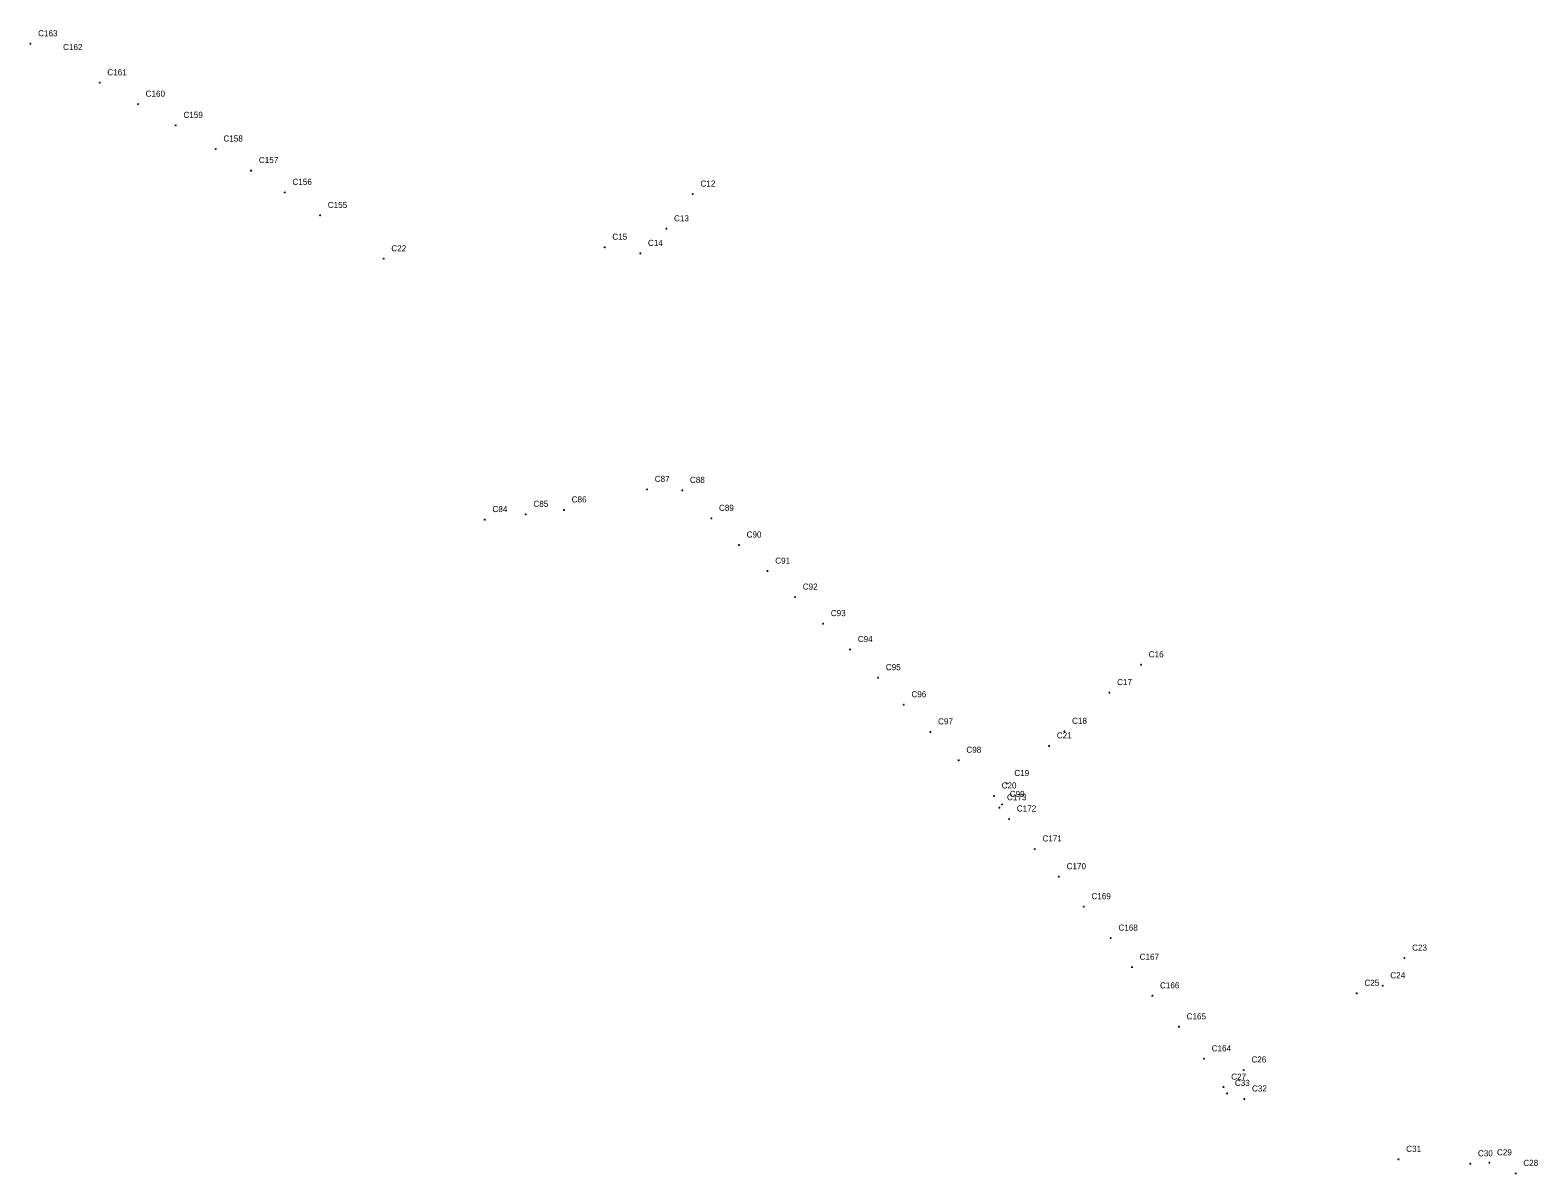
# Model space of a CAD drawing. Extents: x 1725610 to 1734530, y 649909 to 662665.
# Drawn here: x 1730600 to 1731594, y 651651 to 652405 of the extents above; entities that cross this region are included whole.
import ezdxf

# ---------------------------------------------------------------- set-up
doc = ezdxf.new("R2010")
doc.units = 0
doc.layers.add('SURVEY - DRAINAGE - Storm Sewer - Points - Locators', color=7, linetype='Continuous')
doc.layers.add('SURVEY - DRAINAGE - Storm Sewer - Points - Numbers', color=7, linetype='Continuous')

msp = doc.modelspace()

# ---------------------------------------------------------------- linework, layer by layer
at = {"layer": 'SURVEY - DRAINAGE - Storm Sewer - Points - Locators'}
for p, q in [((1730600.75, 652395.63), (1730600.25, 652395.63)), ((1730600.5, 652395.38), (1730600.5, 652395.88)), ((1730600.5, 652395.63), (1730600.5, 652395.63)), ((1730600.5, 652395.63), (1730600.5, 652395.63)), ((1730646.36, 652369.89), (1730645.86, 652369.89)), ((1730646.11, 652369.64), (1730646.11, 652370.14)), ((1730646.11, 652369.89), (1730646.11, 652369.89)), ((1730646.11, 652369.89), (1730646.11, 652369.89)), ((1730671.62, 652355.83), (1730671.12, 652355.83)), ((1730671.37, 652355.58), (1730671.37, 652356.08)), ((1730671.37, 652355.83), (1730671.37, 652355.83)), ((1730671.37, 652355.83), (1730671.37, 652355.83)), ((1730696.58, 652341.83), (1730696.08, 652341.83)), ((1730696.33, 652341.58), (1730696.33, 652342.08)), ((1730696.33, 652341.83), (1730696.33, 652341.83)), ((1730696.33, 652341.83), (1730696.33, 652341.83)), ((1730722.89, 652326.25), (1730722.39, 652326.25)), ((1730722.64, 652326), (1730722.64, 652326.5)), ((1730722.64, 652326.25), (1730722.64, 652326.25)), ((1730722.64, 652326.25), (1730722.64, 652326.25)), ((1730746.28, 652312.03), (1730745.78, 652312.03)), ((1730746.03, 652311.78), (1730746.03, 652312.28)), ((1730746.03, 652312.03), (1730746.03, 652312.03)), ((1730746.03, 652312.03), (1730746.03, 652312.03)), ((1730768.42, 652297.68), (1730767.92, 652297.68)), ((1730768.17, 652297.43), (1730768.17, 652297.93)), ((1730768.17, 652297.68), (1730768.17, 652297.68)), ((1730768.17, 652297.68), (1730768.17, 652297.68)), ((1731037.37, 652296.54), (1731036.87, 652296.54)), ((1731037.12, 652296.29), (1731037.12, 652296.79)), ((1731037.12, 652296.54), (1731037.12, 652296.54)), ((1731037.12, 652296.54), (1731037.12, 652296.54)), ((1730791.71, 652282.41), (1730791.21, 652282.41)), ((1730791.46, 652282.16), (1730791.46, 652282.66)), ((1730791.46, 652282.41), (1730791.46, 652282.41)), ((1730791.46, 652282.41), (1730791.46, 652282.41)), ((1731019.9, 652273.62), (1731019.4, 652273.62)), ((1731019.65, 652273.37), (1731019.65, 652273.87)), ((1731019.65, 652273.62), (1731019.65, 652273.62)), ((1731019.65, 652273.62), (1731019.65, 652273.62)), ((1730833.34, 652253.6), (1730833.34, 652254.1)), ((1730979.24, 652261.48), (1730978.74, 652261.48)), ((1730978.99, 652261.23), (1730978.99, 652261.73)), ((1730978.99, 652261.48), (1730978.99, 652261.48)), ((1730978.99, 652261.48), (1730978.99, 652261.48)), ((1731002.73, 652257.43), (1731002.23, 652257.43)), ((1731002.48, 652257.18), (1731002.48, 652257.68)), ((1731002.48, 652257.43), (1731002.48, 652257.43)), ((1731002.48, 652257.43), (1731002.48, 652257.43)), ((1730833.59, 652253.85), (1730833.09, 652253.85)), ((1730833.34, 652253.85), (1730833.34, 652253.85)), ((1730833.34, 652253.85), (1730833.34, 652253.85)), ((1731007.22, 652101.8), (1731006.72, 652101.8)), ((1731006.97, 652101.55), (1731006.97, 652102.05)), ((1731006.97, 652101.8), (1731006.97, 652101.8)), ((1731006.97, 652101.8), (1731006.97, 652101.8)), ((1731030.4, 652101.15), (1731029.9, 652101.15)), ((1731030.15, 652100.9), (1731030.15, 652101.4)), ((1731030.15, 652101.15), (1731030.15, 652101.15)), ((1731030.15, 652101.15), (1731030.15, 652101.15)), ((1730927.24, 652085.37), (1730926.74, 652085.37)), ((1730926.99, 652085.12), (1730926.99, 652085.62)), ((1730926.99, 652085.37), (1730926.99, 652085.37)), ((1730926.99, 652085.37), (1730926.99, 652085.37)), ((1730952.44, 652088.29), (1730951.94, 652088.29)), ((1730952.19, 652088.04), (1730952.19, 652088.54)), ((1730952.19, 652088.29), (1730952.19, 652088.29)), ((1730952.19, 652088.29), (1730952.19, 652088.29)), ((1730900.25, 652081.91), (1730899.75, 652081.91)), ((1730900, 652081.66), (1730900, 652082.16)), ((1730900, 652081.91), (1730900, 652081.91)), ((1730900, 652081.91), (1730900, 652081.91)), ((1731049.55, 652082.74), (1731049.05, 652082.74)), ((1731049.3, 652082.49), (1731049.3, 652082.99)), ((1731049.3, 652082.74), (1731049.3, 652082.74)), ((1731049.3, 652082.74), (1731049.3, 652082.74)), ((1731067.52, 652064.9), (1731067.52, 652065.4)), ((1731067.77, 652065.15), (1731067.27, 652065.15)), ((1731067.52, 652065.15), (1731067.52, 652065.15)), ((1731067.52, 652065.15), (1731067.52, 652065.15)), ((1731086.63, 652047.91), (1731086.13, 652047.91)), ((1731086.38, 652047.66), (1731086.38, 652048.16)), ((1731086.38, 652047.91), (1731086.38, 652047.91)), ((1731086.38, 652047.91), (1731086.38, 652047.91)), ((1731104.77, 652030.8), (1731104.27, 652030.8)), ((1731104.52, 652030.55), (1731104.52, 652031.05)), ((1731104.52, 652030.8), (1731104.52, 652030.8)), ((1731104.52, 652030.8), (1731104.52, 652030.8)), ((1731123.26, 652013.31), (1731122.76, 652013.31)), ((1731123.01, 652013.06), (1731123.01, 652013.56)), ((1731123.01, 652013.31), (1731123.01, 652013.31)), ((1731123.01, 652013.31), (1731123.01, 652013.31)), ((1731141.07, 651996.21), (1731140.57, 651996.21)), ((1731140.82, 651995.96), (1731140.82, 651996.46)), ((1731140.82, 651996.21), (1731140.82, 651996.21)), ((1731140.82, 651996.21), (1731140.82, 651996.21)), ((1731332.82, 651986.16), (1731332.32, 651986.16)), ((1731332.57, 651985.91), (1731332.57, 651986.41)), ((1731332.57, 651986.16), (1731332.57, 651986.16)), ((1731332.57, 651986.16), (1731332.57, 651986.16)), ((1731159.54, 651977.67), (1731159.04, 651977.67)), ((1731159.29, 651977.42), (1731159.29, 651977.92)), ((1731159.29, 651977.67), (1731159.29, 651977.67)), ((1731159.29, 651977.67), (1731159.29, 651977.67)), ((1731311.98, 651967.82), (1731311.48, 651967.82)), ((1731311.73, 651967.57), (1731311.73, 651968.07)), ((1731311.73, 651967.82), (1731311.73, 651967.82)), ((1731311.73, 651967.82), (1731311.73, 651967.82)), ((1731176.4, 651959.82), (1731175.9, 651959.82)), ((1731176.15, 651959.57), (1731176.15, 651960.07)), ((1731176.15, 651959.82), (1731176.15, 651959.82)), ((1731176.15, 651959.82), (1731176.15, 651959.82)), ((1731193.97, 651941.91), (1731193.47, 651941.91)), ((1731193.72, 651941.66), (1731193.72, 651942.16)), ((1731193.72, 651941.91), (1731193.72, 651941.91)), ((1731193.72, 651941.91), (1731193.72, 651941.91)), ((1731282.27, 651942.28), (1731281.77, 651942.28)), ((1731282.02, 651942.03), (1731282.02, 651942.53)), ((1731282.02, 651942.28), (1731282.02, 651942.28)), ((1731282.02, 651942.28), (1731282.02, 651942.28)), ((1731272.21, 651932.68), (1731271.71, 651932.68)), ((1731271.96, 651932.43), (1731271.96, 651932.93)), ((1731271.96, 651932.68), (1731271.96, 651932.68)), ((1731271.96, 651932.68), (1731271.96, 651932.68)), ((1731212.61, 651923.22), (1731212.11, 651923.22)), ((1731212.36, 651922.97), (1731212.36, 651923.47)), ((1731212.36, 651923.22), (1731212.36, 651923.22)), ((1731212.36, 651923.22), (1731212.36, 651923.22)), ((1731244.24, 651907.88), (1731243.74, 651907.88)), ((1731243.99, 651907.63), (1731243.99, 651908.13)), ((1731243.99, 651907.88), (1731243.99, 651907.88)), ((1731243.99, 651907.88), (1731243.99, 651907.88)), ((1731235.86, 651899.68), (1731235.36, 651899.68)), ((1731235.61, 651899.43), (1731235.61, 651899.93)), ((1731235.61, 651899.68), (1731235.61, 651899.68)), ((1731235.61, 651899.68), (1731235.61, 651899.68)), ((1731239.39, 651891.92), (1731238.89, 651891.92)), ((1731239.14, 651891.67), (1731239.14, 651892.17)), ((1731239.14, 651891.92), (1731239.14, 651891.92)), ((1731239.14, 651891.92), (1731239.14, 651891.92)), ((1731241.21, 651894.09), (1731240.71, 651894.09)), ((1731240.96, 651893.84), (1731240.96, 651894.34)), ((1731240.96, 651894.09), (1731240.96, 651894.09)), ((1731240.96, 651894.09), (1731240.96, 651894.09)), ((1731245.9, 651884.48), (1731245.4, 651884.48)), ((1731245.65, 651884.23), (1731245.65, 651884.73)), ((1731245.65, 651884.48), (1731245.65, 651884.48)), ((1731245.65, 651884.48), (1731245.65, 651884.48)), ((1731262.75, 651864.73), (1731262.25, 651864.73)), ((1731262.5, 651864.48), (1731262.5, 651864.98)), ((1731262.5, 651864.73), (1731262.5, 651864.73)), ((1731262.5, 651864.73), (1731262.5, 651864.73)), ((1731278.43, 651846.19), (1731278.43, 651846.69)), ((1731278.68, 651846.44), (1731278.18, 651846.44)), ((1731278.43, 651846.44), (1731278.43, 651846.44)), ((1731278.43, 651846.44), (1731278.43, 651846.44)), ((1731295.08, 651826.68), (1731294.58, 651826.68)), ((1731294.83, 651826.43), (1731294.83, 651826.93)), ((1731294.83, 651826.68), (1731294.83, 651826.68)), ((1731294.83, 651826.68), (1731294.83, 651826.68)), ((1731312.84, 651805.95), (1731312.34, 651805.95)), ((1731312.59, 651805.7), (1731312.59, 651806.2)), ((1731312.59, 651805.95), (1731312.59, 651805.95)), ((1731312.59, 651805.95), (1731312.59, 651805.95)), ((1731326.59, 651786.51), (1731326.59, 651787.01)), ((1731506.42, 651792.75), (1731505.92, 651792.75)), ((1731506.17, 651792.5), (1731506.17, 651793)), ((1731506.17, 651792.75), (1731506.17, 651792.75)), ((1731506.17, 651792.75), (1731506.17, 651792.75)), ((1731326.84, 651786.76), (1731326.34, 651786.76)), ((1731326.59, 651786.76), (1731326.59, 651786.76)), ((1731326.59, 651786.76), (1731326.59, 651786.76)), ((1731340.25, 651767.87), (1731339.75, 651767.87)), ((1731340, 651767.62), (1731340, 651768.12)), ((1731340, 651767.87), (1731340, 651767.87)), ((1731340, 651767.87), (1731340, 651767.87)), ((1731475, 651769.58), (1731474.5, 651769.58)), ((1731474.75, 651769.33), (1731474.75, 651769.83)), ((1731474.75, 651769.58), (1731474.75, 651769.58)), ((1731474.75, 651769.58), (1731474.75, 651769.58)), ((1731492.07, 651774.48), (1731491.57, 651774.48)), ((1731491.82, 651774.23), (1731491.82, 651774.73)), ((1731491.82, 651774.48), (1731491.82, 651774.48)), ((1731491.82, 651774.48), (1731491.82, 651774.48)), ((1731357.81, 651747.43), (1731357.31, 651747.43)), ((1731357.56, 651747.18), (1731357.56, 651747.68)), ((1731357.56, 651747.43), (1731357.56, 651747.43)), ((1731357.56, 651747.43), (1731357.56, 651747.43)), ((1731374.31, 651726.36), (1731373.81, 651726.36)), ((1731374.06, 651726.11), (1731374.06, 651726.61)), ((1731374.06, 651726.36), (1731374.06, 651726.36)), ((1731374.06, 651726.36), (1731374.06, 651726.36)), ((1731400.52, 651719.02), (1731400.02, 651719.02)), ((1731400.27, 651718.77), (1731400.27, 651719.27)), ((1731400.27, 651719.02), (1731400.27, 651719.02)), ((1731400.27, 651719.02), (1731400.27, 651719.02)), ((1731387.21, 651707.68), (1731386.71, 651707.68)), ((1731386.96, 651707.43), (1731386.96, 651707.93)), ((1731386.96, 651707.68), (1731386.96, 651707.68)), ((1731386.96, 651707.68), (1731386.96, 651707.68)), ((1731389.64, 651703.55), (1731389.14, 651703.55)), ((1731389.39, 651703.3), (1731389.39, 651703.8)), ((1731389.39, 651703.55), (1731389.39, 651703.55)), ((1731389.39, 651703.55), (1731389.39, 651703.55)), ((1731400.87, 651699.89), (1731400.37, 651699.89)), ((1731400.62, 651699.64), (1731400.62, 651700.14)), ((1731400.62, 651699.89), (1731400.62, 651699.89)), ((1731400.62, 651699.89), (1731400.62, 651699.89)), ((1731502.55, 651660.09), (1731502.05, 651660.09)), ((1731502.3, 651659.84), (1731502.3, 651660.34)), ((1731502.3, 651660.09), (1731502.3, 651660.09)), ((1731502.3, 651660.09), (1731502.3, 651660.09)), ((1731562.38, 651657.79), (1731561.88, 651657.79)), ((1731562.13, 651657.54), (1731562.13, 651658.04)), ((1731562.13, 651657.79), (1731562.13, 651657.79)), ((1731562.13, 651657.79), (1731562.13, 651657.79)), ((1731549.83, 651657.15), (1731549.33, 651657.15)), ((1731549.58, 651656.9), (1731549.58, 651657.4)), ((1731549.58, 651657.15), (1731549.58, 651657.15)), ((1731549.58, 651657.15), (1731549.58, 651657.15)), ((1731579.74, 651650.83), (1731579.24, 651650.83)), ((1731579.49, 651650.58), (1731579.49, 651651.08)), ((1731579.49, 651650.83), (1731579.49, 651650.83)), ((1731579.49, 651650.83), (1731579.49, 651650.83))]:
    msp.add_line(p, q, dxfattribs=at)

# ---------------------------------------------------------------- texts
at = {"layer": 'SURVEY - DRAINAGE - Storm Sewer - Points - Numbers'}
for s, p in [('C163', (1730605.5, 652400.63)), ('C162', (1730621.94, 652391.56)), ('C161', (1730651.11, 652374.89)), ('C160', (1730676.37, 652360.83)), ('C159', (1730701.33, 652346.83)), ('C158', (1730727.64, 652331.25)), ('C157', (1730751.03, 652317.03)), ('C156', (1730773.17, 652302.68)), ('C12', (1731042.12, 652301.54)), ('C155', (1730796.46, 652287.41)), ('C13', (1731024.65, 652278.62)), ('C15', (1730983.99, 652266.48)), ('C14', (1731007.48, 652262.43)), ('C22', (1730838.34, 652258.85)), ('C87', (1731011.97, 652106.8)), ('C88', (1731035.15, 652106.15)), ('C86', (1730957.19, 652093.29)), ('C84', (1730905, 652086.91)), ('C85', (1730931.99, 652090.37)), ('C89', (1731054.3, 652087.74)), ('C90', (1731072.52, 652070.15)), ('C91', (1731091.38, 652052.91)), ('C92', (1731109.52, 652035.8)), ('C93', (1731128.01, 652018.31)), ('C94', (1731145.82, 652001.21)), ('C95', (1731164.29, 651982.67)), ('C16', (1731337.57, 651991.16)), ('C17', (1731316.73, 651972.82)), ('C96', (1731181.15, 651964.82)), ('C97', (1731198.72, 651946.91)), ('C18', (1731287.02, 651947.28)), ('C21', (1731276.96, 651937.68)), ('C98', (1731217.36, 651928.22)), ('C19', (1731248.99, 651912.88)), ('C20', (1731240.61, 651904.68)), ('C173', (1731244.14, 651896.92)), ('C99', (1731245.96, 651899.09)), ('C172', (1731250.65, 651889.48)), ('C171', (1731267.5, 651869.73)), ('C170', (1731283.43, 651851.44)), ('C169', (1731299.83, 651831.68)), ('C168', (1731317.59, 651810.95)), ('C23', (1731511.17, 651797.75)), ('C167', (1731331.59, 651791.76)), ('C25', (1731479.75, 651774.58)), ('C24', (1731496.82, 651779.48)), ('C166', (1731345, 651772.87)), ('C165', (1731362.56, 651752.43)), ('C164', (1731379.06, 651731.36)), ('C26', (1731405.27, 651724.02)), ('C27', (1731391.96, 651712.68)), ('C33', (1731394.39, 651708.55)), ('C32', (1731405.62, 651704.89)), ('C31', (1731507.3, 651665.09)), ('C30', (1731554.58, 651662.15)), ('C29', (1731567.13, 651662.79)), ('C28', (1731584.49, 651655.83))]:
    msp.add_text(s, height=4, dxfattribs=at).set_placement(p)

doc.saveas('drawing.dxf')
